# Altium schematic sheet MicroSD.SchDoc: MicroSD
size A4; DocumentNumber: MB1144; Revision: B-02; SheetNumber: 14; SheetTotal: 25; Project: STM32L476G-EVAL
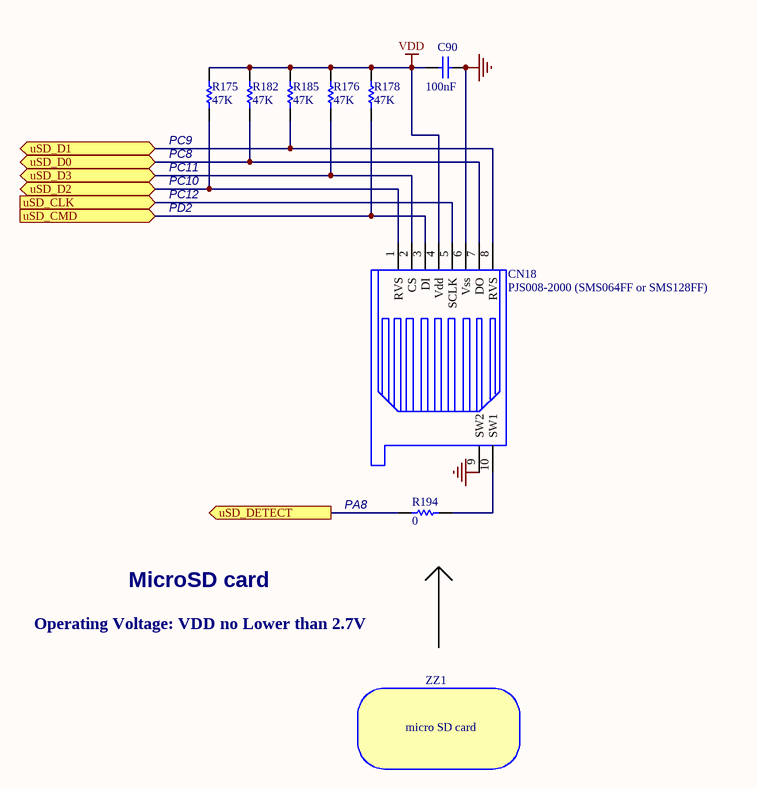
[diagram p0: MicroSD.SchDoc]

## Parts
C90  100nF  [0402C]
CN18  PJS008-2000 (SMS064FF or SMS128FF)  [MSD_PJS008_]
R175  47K  [0402R]
R176  47K  [0402R]
R178  47K  [0402R]
R182  47K  [0402R]
R185  47K  [0402R]
R194  0  [0603R]
ZZ1  micro SD card

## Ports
uSD_CLK (in), uSD_CMD (in), uSD_D0 (bidir), uSD_D1 (bidir), uSD_D2 (bidir), uSD_D3 (bidir), uSD_DETECT (out)

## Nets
GND: C90.2 CN18.6(Vss) CN18.9(SW2)
VDD: C90.1 CN18.4(Vdd) R175.1 R176.1 R178.1 R182.1 R185.1
uSD_CLK: CN18.5(SCLK) ; port uSD_CLK
uSD_CMD: CN18.3(DI) R178.2 ; port uSD_CMD
uSD_D0: CN18.7(DO) R182.2 ; port uSD_D0
uSD_D1: CN18.8(RVS) R185.2 ; port uSD_D1
uSD_D2: CN18.1(RVS) R175.2 ; port uSD_D2
uSD_D3: CN18.2(CS) R176.2 ; port uSD_D3
uSD_DETECT: R194.1 ; port uSD_DETECT
NetCN18_10: CN18.10(SW1) R194.2

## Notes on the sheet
- (near R175) PC9
- (near R175) PC8
- PC10
- PC11
- PC12
- PD2
- PA8
- MicroSD card
- Operating Voltage: VDD no Lower than 2.7V

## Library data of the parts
C90 = CAP: Capacitor; Value: 100pF; Ordered by: Subcon; ECCN_US/EU: NA
CN18 = SMS016AFA5E: ECCN_US/EU: NA; Ordered by: Subcon; Assembly: with SD card; Comments: Micro SD card connector
R175 R176 R178 R182 R185 R194 = Res1: Resistor; Value: 1K; Ordered by: Subcon; ECCN_US/EU: NA
ZZ1 = BoM_Item: 4GB or more; Ordered by: Subcon; Assembly: to plug in CN18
